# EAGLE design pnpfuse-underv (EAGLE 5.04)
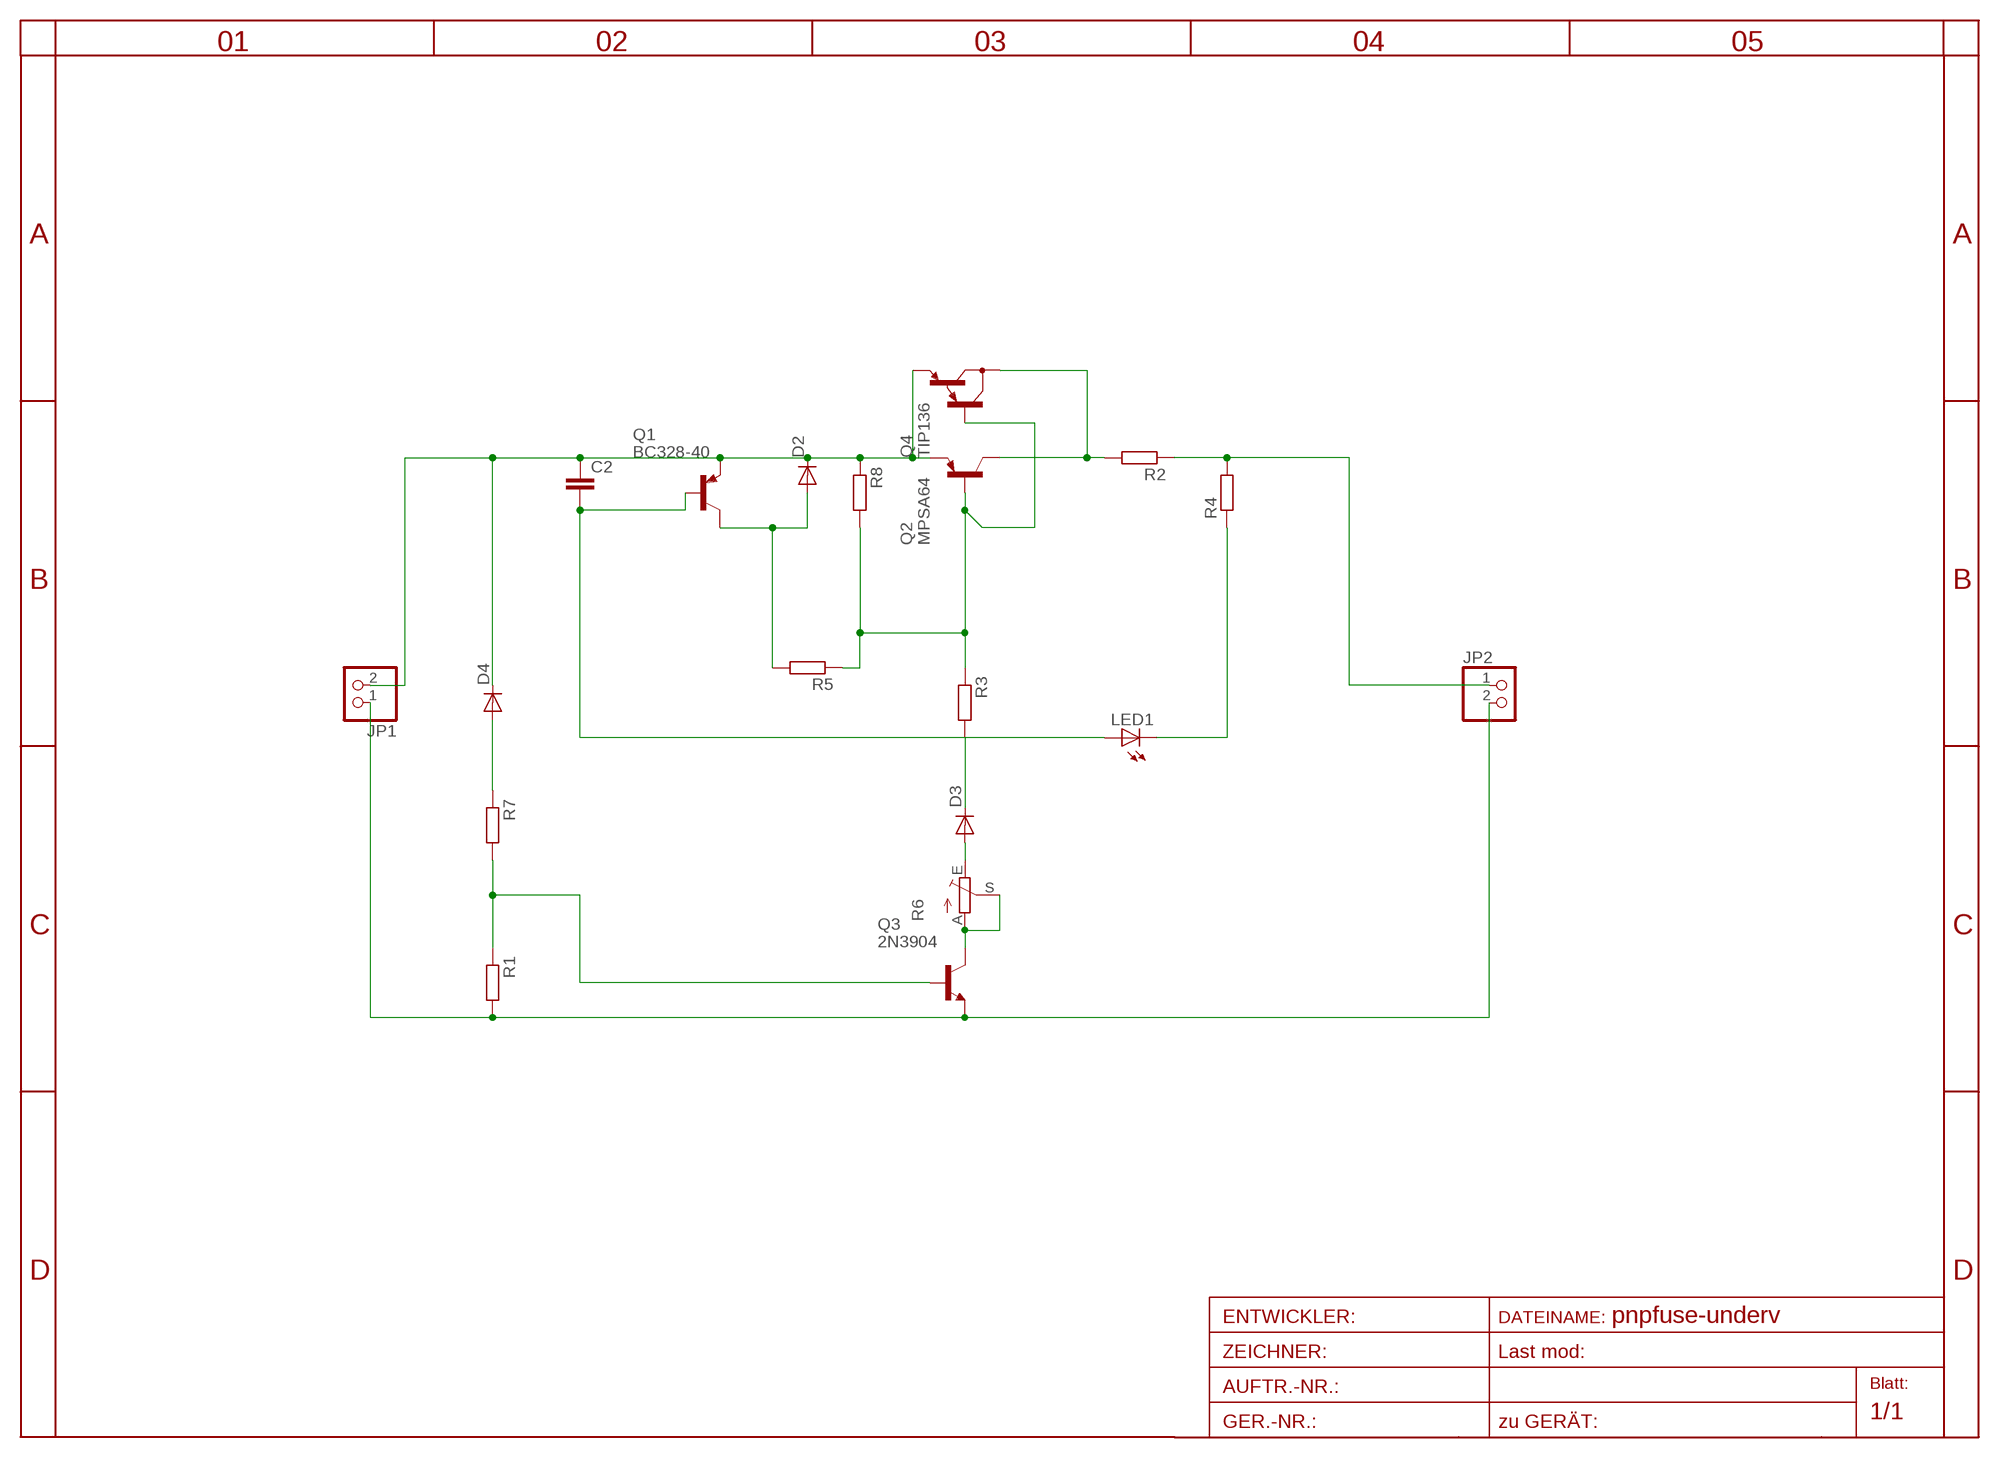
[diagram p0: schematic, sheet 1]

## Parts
C2  C-EU025-024X044  [C025-024X044]
D2  DIODE-D-5  [D-5]
D3  DIODE-D-5  [D-5]
D4  DIODE-D-5  [D-5]
JP1  PINHD-1X2  [1X02]
JP2  PINHD-1X2  [1X02]
LED1  LED3MM  [LED3MM]
Q1  BC328-40  [TO92-EBC]
Q2  MPSA64  [TO92-CBE]
Q3  2N3904  [TO92]
Q4  TIP136  [TO220]
R1  R-EU_0204/7  [0204/7]
R2  R-EU_0204/5  [0204/5]
R3  R-EU_0204/7  [0204/7]
R4  R-EU_0207/12  [0207/12]
R5  R-EU_0204/5  [0204/5]
R6  TRIM_EU-CA6V  [CA6V]
R7  R-EU_0204/7  [0204/7]
R8  R-EU_0204/7  [0204/7]

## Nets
N$1: JP1.1 JP2.2 Q3.3(E) R1.2
N$2: C2.1 D2.C D4.C JP1.2 Q1.E Q2.E Q4.3(E) R8.1
N$3: D4.A R7.1
N$4: D2.A Q1.C R5.2
N$5: D3.C R3.2
N$6: D3.A R6.E
N$7: Q2.B Q4.1(B) R3.1 R5.1 R8.2
N$8: JP2.1 R2.1 R4.2
N$9: Q3.1(C) R6.A R6.S
N$10: Q2.C Q4.2(C) R2.2
N$11: LED1.K(C) R4.1
N$12: C2.2 LED1.A Q1.B
N$13: Q3.2(B) R1.1 R7.2

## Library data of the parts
C2 = rcl-2:C-EU: CAPACITOR, European symbol
D2-D4 = diode-1:DIODE-: DIODE
JP1 JP2 = pinhead:PINHD-1X2: PIN HEADER
LED1 = led:LED: LED
Q1 = transistor-pnp:BC328*: PNP Transistror
Q2 = transistor-pnp:MPSA64*: PNP Transistror
Q3 = transistor-npn:2N3904: NPN Transistor
Q4 = transistor-pnp:TIP136: PNP Darlington Transistor
R1-R5 R7 R8 = rcl-2:R-EU_: RESISTOR, European symbol
R6 = pot:TRIM_EU-: POTENTIOMETER

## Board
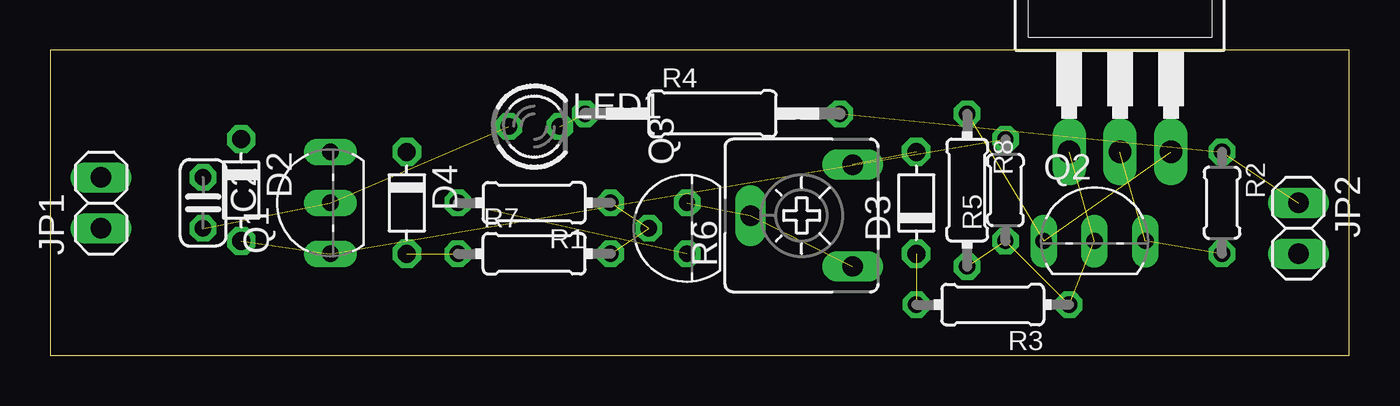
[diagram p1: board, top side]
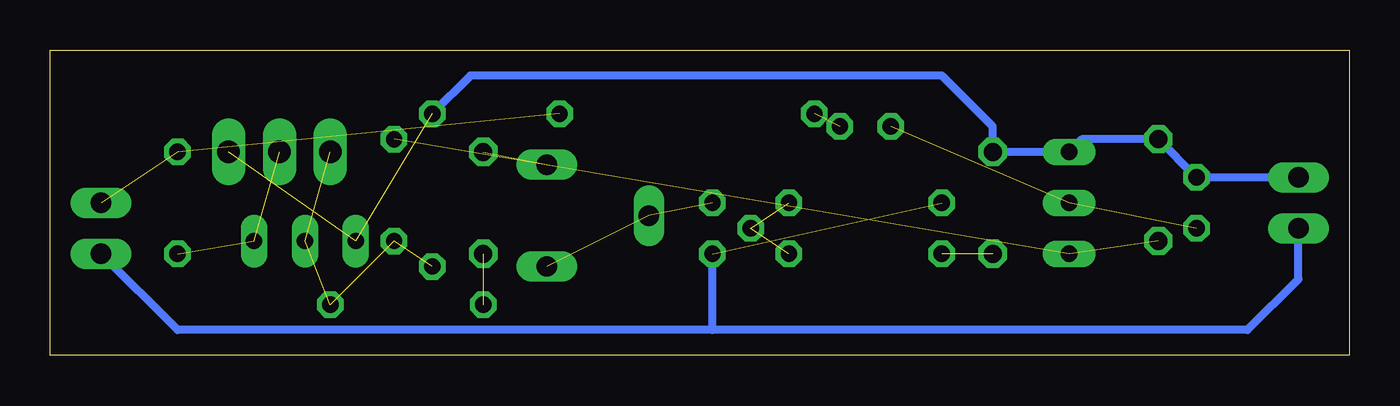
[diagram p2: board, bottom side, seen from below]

Size 64.77 x 15.24 mm. Coordinates in mm from the lower left corner, seen from the top.
Outline: 0,0 64.77,0 64.77,15.24 0,15.24 0,0
Copper layers (1*16): Top 0.035mm / dielectric 1.5mm / Bottom 0.035mm
Design rules "default": minimum track width 10mil, minimum drill 24mil, track to track 8mil, track to pad 8mil, pad to pad 8mil, via to via 8mil, smd to smd 8mil, copper to edge 40mil, drill to drill 8mil, minimum pad ring 10mil, minimum via ring 8mil, stop-mask expansion 4mil, vias tented up to drill 0mil, thermal gap 10mil

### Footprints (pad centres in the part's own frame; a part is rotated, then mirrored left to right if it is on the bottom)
C025-024X044 = drill 0.813 octagon: 1 -1.27,0; 2 1.27,0
D-5 = drill 0.9 octagon: A 2.54,0; C -2.54,0
1X02 = drill 1.016 long: 1 -1.27,0; 2 1.27,0
LED3MM = drill 0.813 octagon: A -1.27,0; K 1.27,0
TO92-EBC = drill 0.813 long: B 0,-1.27; C -2.54,-1.27; E 2.54,-1.27
TO92-CBE = drill 0.813 long: B 0,0; C 2.54,0; E -2.54,0
TO92 = drill 0.813 octagon: 1 1.27,0; 2 0,1.905; 3 -1.27,0
TO220 = drill 1.118 long: 1 -2.54,-6.35; 2 0,-6.35; 3 2.54,-6.35 | hole 3.302: 0,11.176
0204/7 = drill 0.813 octagon: 1 -3.81,0; 2 3.81,0
0204/5 = drill 0.813 octagon: 1 -2.54,0; 2 2.54,0
0207/12 = drill 0.813 octagon: 1 -6.35,0; 2 6.35,0
CA6V = drill 1.016 long: A -2.54,-2.54; E 2.54,-2.54; S 0,2.54

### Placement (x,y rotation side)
C2  7.62,7.62 270 top
D2  9.53,8.26 270 top
D3  43.18,7.62 90 top
D4  17.78,7.62 270 top
JP1  2.54,7.62 90 top
JP2  62.23,6.35 270 top
LED1  24.13,11.43 0 top
Q1  12.7,7.62 90 top
Q2  52.07,5.71 0 top
Q3  31.75,6.35 90 top
Q4  53.34,16.51 0 top
R1  24.13,7.62 180 top
R2  58.42,7.62 270 top
R3  46.99,2.54 180 top
R4  33.02,12.06 0 top
R5  47.62,8.26 90 top
R6  37.47,6.99 90 top
R7  24.13,5.08 0 top
R8  45.72,8.26 270 top

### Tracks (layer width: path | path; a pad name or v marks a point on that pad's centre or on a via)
N$1  (1 unrouted)
  Bottom 0.406: JP1.1 2.54,3.81 5.08,1.27 31.75,1.27 | 31.75,1.27 58.42,1.27 JP2.2 | 31.75,1.27 Q3.3
N$2  (2 unrouted)
  Bottom 0.406: JP1.2 C2.1 D2.C 13.34,10.79 Q1.E D4.C 17.78,11.43 20.32,13.97 43.81,13.97 R8.1
N$3  (1 unrouted)
N$4  (2 unrouted)
N$5  (1 unrouted)
N$6  (1 unrouted)
N$7  (4 unrouted)
N$8  (2 unrouted)
N$9  (2 unrouted)
N$10  (2 unrouted)
N$11  (1 unrouted)
N$12  (2 unrouted)
N$13  (2 unrouted)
